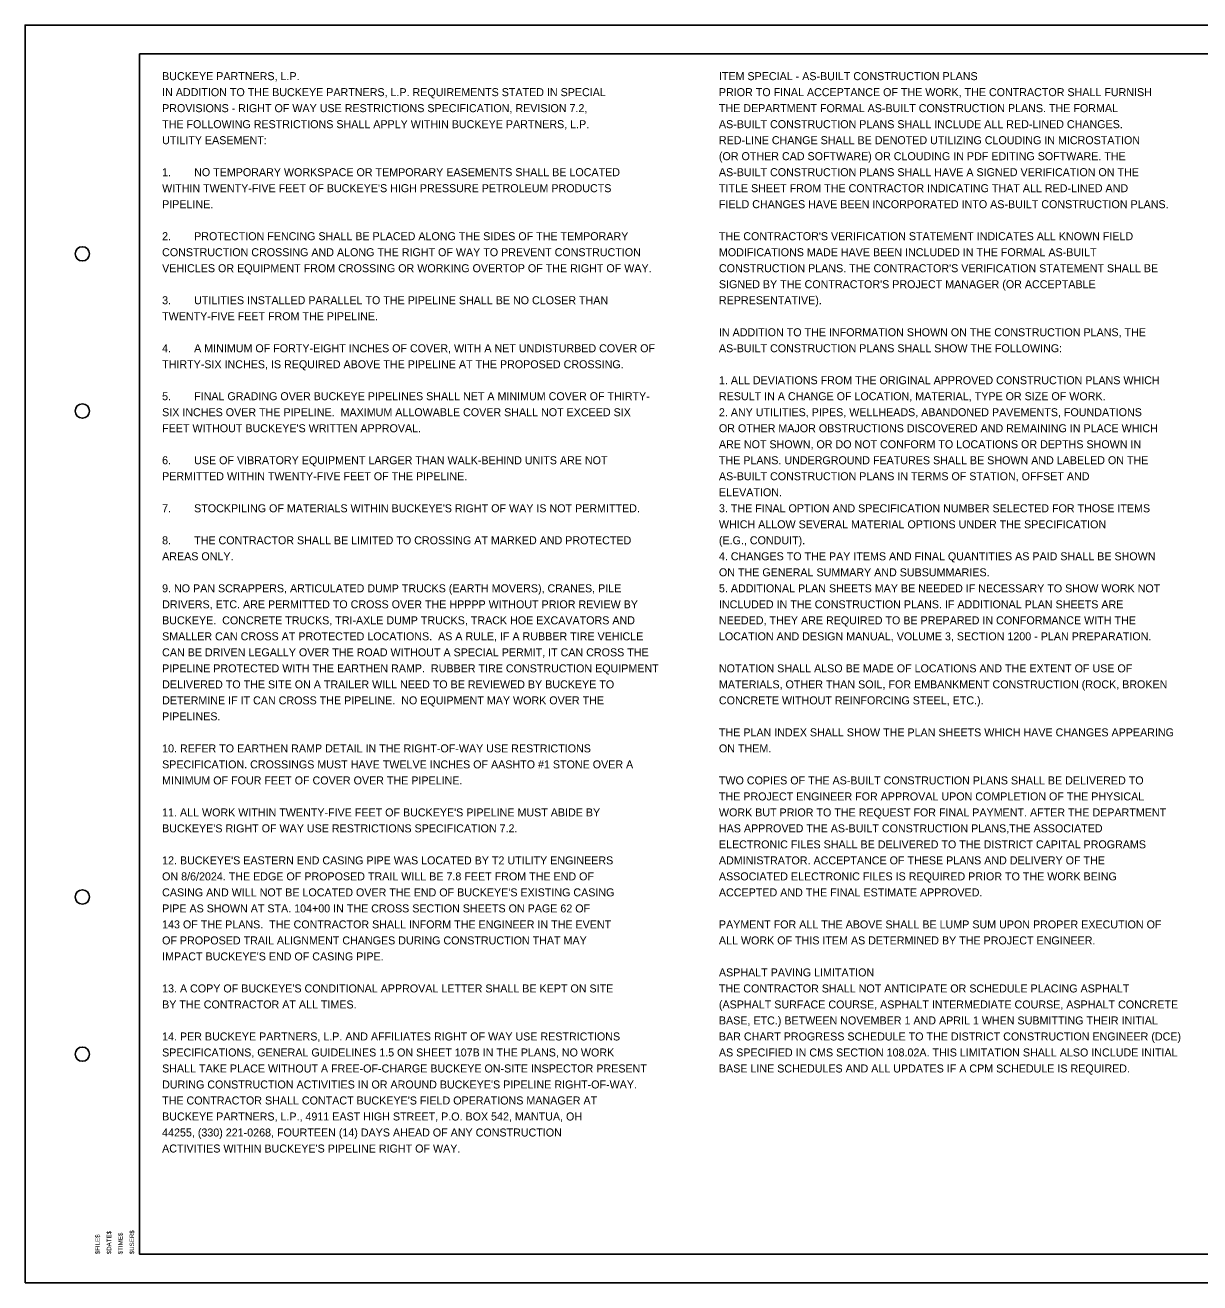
# Model space of a CAD drawing. Extents: x -16 to 195, y -13 to 9.
# Drawn here: x 160.56 to 181.1, y -12.91 to 9.09 of the extents above; entities that cross this region are included whole.
import ezdxf

# ---------------------------------------------------------------- set-up
doc = ezdxf.new("R2010")
doc.units = 0
for name, color, linetype in [('SH_Border', 7, 'Continuous'), ('SH_Cut_Line', 7, 'Continuous'), ('TX_P_1', 7, 'Continuous'), ('TX_P_Misc', 7, 'Continuous')]:
    doc.layers.add(name, color=color, linetype=linetype)

msp = doc.modelspace()

# ---------------------------------------------------------------- linework, layer by layer
at = {"layer": 'SH_Border'}
msp.add_lwpolyline([(162.559, 8.593), (194.059, 8.593), (194.059, -12.407), (162.559, -12.407)], close=True, dxfattribs=at)
for centre in [(161.559, 5.093), (161.559, 2.343), (161.559, -6.157), (161.559, -8.907)]:
    msp.add_circle(centre, 0.125, dxfattribs=at)
at = {"layer": 'SH_Cut_Line'}
msp.add_lwpolyline([(160.559, -12.907), (194.559, -12.907), (194.559, 9.093), (160.559, 9.093)], close=True, dxfattribs=at)

# ---------------------------------------------------------------- texts
at = {"layer": 'TX_P_1'}
for s, p in [('BUCKEYE PARTNERS, L.P.', (162.954, 8.131)), ('ITEM SPECIAL - AS-BUILT CONSTRUCTION PLANS', (172.692, 8.131)), ('IN ADDITION TO THE BUCKEYE PARTNERS, L.P. REQUIREMENTS STATED IN SPECIAL', (162.954, 7.851)), ('PRIOR TO FINAL ACCEPTANCE OF THE WORK, THE CONTRACTOR SHALL FURNISH', (172.692, 7.851)), ('PROVISIONS - RIGHT OF WAY USE RESTRICTIONS SPECIFICATION, REVISION 7.2,', (162.954, 7.571)), ('THE DEPARTMENT FORMAL AS-BUILT CONSTRUCTION PLANS. THE FORMAL', (172.692, 7.571)), ('THE FOLLOWING RESTRICTIONS SHALL APPLY WITHIN BUCKEYE PARTNERS, L.P.', (162.954, 7.291)), ('AS-BUILT CONSTRUCTION PLANS SHALL INCLUDE ALL RED-LINED CHANGES.', (172.692, 7.291)), ('UTILITY EASEMENT:', (162.954, 7.011)), ('RED-LINE CHANGE SHALL BE DENOTED UTILIZING CLOUDING IN MICROSTATION', (172.692, 7.011)), ('(OR OTHER CAD SOFTWARE) OR CLOUDING IN PDF EDITING SOFTWARE. THE', (172.692, 6.731)), ('1.', (162.954, 6.451)), ('NO TEMPORARY WORKSPACE OR TEMPORARY EASEMENTS SHALL BE LOCATED', (163.514, 6.451)), ('AS-BUILT CONSTRUCTION PLANS SHALL HAVE A SIGNED VERIFICATION ON THE', (172.692, 6.451)), ("WITHIN TWENTY-FIVE FEET OF BUCKEYE'S HIGH PRESSURE PETROLEUM PRODUCTS", (162.954, 6.171)), ('TITLE SHEET FROM THE CONTRACTOR INDICATING THAT ALL RED-LINED AND', (172.692, 6.171)), ('PIPELINE.', (162.954, 5.891)), ('FIELD CHANGES HAVE BEEN INCORPORATED INTO AS-BUILT CONSTRUCTION PLANS.', (172.692, 5.891)), ('2.', (162.954, 5.331)), ('PROTECTION FENCING SHALL BE PLACED ALONG THE SIDES OF THE TEMPORARY', (163.514, 5.331)), ("THE CONTRACTOR'S VERIFICATION STATEMENT INDICATES ALL KNOWN FIELD", (172.692, 5.331)), ('CONSTRUCTION CROSSING AND ALONG THE RIGHT OF WAY TO PREVENT CONSTRUCTION', (162.954, 5.051)), ('MODIFICATIONS MADE HAVE BEEN INCLUDED IN THE FORMAL AS-BUILT', (172.692, 5.051)), ('VEHICLES OR EQUIPMENT FROM CROSSING OR WORKING OVERTOP OF THE RIGHT OF WAY.', (162.954, 4.771)), ("CONSTRUCTION PLANS. THE CONTRACTOR'S VERIFICATION STATEMENT SHALL BE", (172.692, 4.771)), ("SIGNED BY THE CONTRACTOR'S PROJECT MANAGER (OR ACCEPTABLE", (172.692, 4.491)), ('3.', (162.954, 4.211)), ('UTILITIES INSTALLED PARALLEL TO THE PIPELINE SHALL BE NO CLOSER THAN', (163.514, 4.211)), ('REPRESENTATIVE).', (172.692, 4.211)), ('TWENTY-FIVE FEET FROM THE PIPELINE.', (162.954, 3.931)), ('IN ADDITION TO THE INFORMATION SHOWN ON THE CONSTRUCTION PLANS, THE', (172.692, 3.651)), ('4.', (162.954, 3.371)), ('A MINIMUM OF FORTY-EIGHT INCHES OF COVER, WITH A NET UNDISTURBED COVER OF', (163.514, 3.371)), ('AS-BUILT CONSTRUCTION PLANS SHALL SHOW THE FOLLOWING:', (172.692, 3.371)), ('THIRTY-SIX INCHES, IS REQUIRED ABOVE THE PIPELINE AT THE PROPOSED CROSSING.', (162.954, 3.091)), ('1. ALL DEVIATIONS FROM THE ORIGINAL APPROVED CONSTRUCTION PLANS WHICH', (172.692, 2.812)), ('5.', (162.954, 2.532)), ('FINAL GRADING OVER BUCKEYE PIPELINES SHALL NET A MINIMUM COVER OF THIRTY-', (163.514, 2.532)), ('RESULT IN A CHANGE OF LOCATION, MATERIAL, TYPE OR SIZE OF WORK.', (172.692, 2.532)), ('SIX INCHES OVER THE PIPELINE.  MAXIMUM ALLOWABLE COVER SHALL NOT EXCEED SIX', (162.954, 2.252)), ('2. ANY UTILITIES, PIPES, WELLHEADS, ABANDONED PAVEMENTS, FOUNDATIONS', (172.692, 2.252)), ("FEET WITHOUT BUCKEYE'S WRITTEN APPROVAL.  ", (162.954, 1.972)), ('OR OTHER MAJOR OBSTRUCTIONS DISCOVERED AND REMAINING IN PLACE WHICH', (172.692, 1.972)), ('ARE NOT SHOWN, OR DO NOT CONFORM TO LOCATIONS OR DEPTHS SHOWN IN', (172.692, 1.692)), ('6.', (162.954, 1.412)), ('USE OF VIBRATORY EQUIPMENT LARGER THAN WALK-BEHIND UNITS ARE NOT', (163.514, 1.412)), ('THE PLANS. UNDERGROUND FEATURES SHALL BE SHOWN AND LABELED ON THE ', (172.692, 1.412)), ('PERMITTED WITHIN TWENTY-FIVE FEET OF THE PIPELINE.', (162.954, 1.132)), ('AS-BUILT CONSTRUCTION PLANS IN TERMS OF STATION, OFFSET AND', (172.692, 1.132)), ('ELEVATION.', (172.692, 0.852)), ('7.', (162.954, 0.572)), ("STOCKPILING OF MATERIALS WITHIN BUCKEYE'S RIGHT OF WAY IS NOT PERMITTED.", (163.514, 0.572)), ('3. THE FINAL OPTION AND SPECIFICATION NUMBER SELECTED FOR THOSE ITEMS', (172.692, 0.572)), ('WHICH ALLOW SEVERAL MATERIAL OPTIONS UNDER THE SPECIFICATION', (172.692, 0.292)), ('8.', (162.954, 0.012)), ('THE CONTRACTOR SHALL BE LIMITED TO CROSSING AT MARKED AND PROTECTED', (163.514, 0.012)), ('(E.G., CONDUIT).', (172.692, 0.012)), ('AREAS ONLY.', (162.954, -0.268)), ('4. CHANGES TO THE PAY ITEMS AND FINAL QUANTITIES AS PAID SHALL BE SHOWN', (172.692, -0.268)), ('ON THE GENERAL SUMMARY AND SUBSUMMARIES.', (172.692, -0.548)), ('9. NO PAN SCRAPPERS, ARTICULATED DUMP TRUCKS (EARTH MOVERS), CRANES, PILE', (162.954, -0.828)), ('5. ADDITIONAL PLAN SHEETS MAY BE NEEDED IF NECESSARY TO SHOW WORK NOT', (172.692, -0.828)), ('DRIVERS, ETC. ARE PERMITTED TO CROSS OVER THE HPPPP WITHOUT PRIOR REVIEW BY', (162.954, -1.108)), ('INCLUDED IN THE CONSTRUCTION PLANS. IF ADDITIONAL PLAN SHEETS ARE', (172.692, -1.108)), ('BUCKEYE.  CONCRETE TRUCKS, TRI-AXLE DUMP TRUCKS, TRACK HOE EXCAVATORS AND', (162.954, -1.388)), ('NEEDED, THEY ARE REQUIRED TO BE PREPARED IN CONFORMANCE WITH THE', (172.692, -1.388)), ('SMALLER CAN CROSS AT PROTECTED LOCATIONS.  AS A RULE, IF A RUBBER TIRE VEHICLE', (162.954, -1.668)), ('LOCATION AND DESIGN MANUAL, VOLUME 3, SECTION 1200 - PLAN PREPARATION.', (172.692, -1.668)), ('CAN BE DRIVEN LEGALLY OVER THE ROAD WITHOUT A SPECIAL PERMIT, IT CAN CROSS THE', (162.954, -1.948)), ('PIPELINE PROTECTED WITH THE EARTHEN RAMP.  RUBBER TIRE CONSTRUCTION EQUIPMENT ', (162.954, -2.228)), ('NOTATION SHALL ALSO BE MADE OF LOCATIONS AND THE EXTENT OF USE OF', (172.692, -2.228)), ('DELIVERED TO THE SITE ON A TRAILER WILL NEED TO BE REVIEWED BY BUCKEYE TO', (162.954, -2.508)), ('MATERIALS, OTHER THAN SOIL, FOR EMBANKMENT CONSTRUCTION (ROCK, BROKEN', (172.692, -2.508)), ('DETERMINE IF IT CAN CROSS THE PIPELINE.  NO EQUIPMENT MAY WORK OVER THE', (162.954, -2.788)), ('CONCRETE WITHOUT REINFORCING STEEL, ETC.).', (172.692, -2.788)), ('PIPELINES. ', (162.954, -3.068)), ('THE PLAN INDEX SHALL SHOW THE PLAN SHEETS WHICH HAVE CHANGES APPEARING', (172.692, -3.348)), ('10. REFER TO EARTHEN RAMP DETAIL IN THE RIGHT-OF-WAY USE RESTRICTIONS', (162.954, -3.628)), ('ON THEM.', (172.692, -3.628)), ('SPECIFICATION. CROSSINGS MUST HAVE TWELVE INCHES OF AASHTO #1 STONE OVER A', (162.954, -3.908)), ('MINIMUM OF FOUR FEET OF COVER OVER THE PIPELINE. ', (162.954, -4.188)), ('TWO COPIES OF THE AS-BUILT CONSTRUCTION PLANS SHALL BE DELIVERED TO', (172.692, -4.188)), ('THE PROJECT ENGINEER FOR APPROVAL UPON COMPLETION OF THE PHYSICAL', (172.692, -4.468)), ("11. ALL WORK WITHIN TWENTY-FIVE FEET OF BUCKEYE'S PIPELINE MUST ABIDE BY", (162.954, -4.748)), ('WORK BUT PRIOR TO THE REQUEST FOR FINAL PAYMENT. AFTER THE DEPARTMENT', (172.692, -4.748)), ("BUCKEYE'S RIGHT OF WAY USE RESTRICTIONS SPECIFICATION 7.2. ", (162.954, -5.027)), ('HAS APPROVED THE AS-BUILT CONSTRUCTION PLANS,THE ASSOCIATED', (172.692, -5.027)), ('ELECTRONIC FILES SHALL BE DELIVERED TO THE DISTRICT CAPITAL PROGRAMS', (172.692, -5.307)), ("12. BUCKEYE'S EASTERN END CASING PIPE WAS LOCATED BY T2 UTILITY ENGINEERS", (162.954, -5.587)), ('ADMINISTRATOR. ACCEPTANCE OF THESE PLANS AND DELIVERY OF THE ', (172.692, -5.587)), ('ON 8/6/2024. THE EDGE OF PROPOSED TRAIL WILL BE 7.8 FEET FROM THE END OF', (162.954, -5.867)), ('ASSOCIATED ELECTRONIC FILES IS REQUIRED PRIOR TO THE WORK BEING', (172.692, -5.867)), ("CASING AND WILL NOT BE LOCATED OVER THE END OF BUCKEYE'S EXISTING CASING", (162.954, -6.147)), ('ACCEPTED AND THE FINAL ESTIMATE APPROVED.', (172.692, -6.147)), ('PIPE AS SHOWN AT STA. 104+00 IN THE CROSS SECTION SHEETS ON PAGE 62 OF ', (162.954, -6.427)), ('143 OF THE PLANS.  THE CONTRACTOR SHALL INFORM THE ENGINEER IN THE EVENT', (162.954, -6.707)), ('PAYMENT FOR ALL THE ABOVE SHALL BE LUMP SUM UPON PROPER EXECUTION OF', (172.692, -6.707)), ('OF PROPOSED TRAIL ALIGNMENT CHANGES DURING CONSTRUCTION THAT MAY', (162.954, -6.987)), ('ALL WORK OF THIS ITEM AS DETERMINED BY THE PROJECT ENGINEER. ', (172.692, -6.987)), ("IMPACT BUCKEYE'S END OF CASING PIPE.", (162.954, -7.267)), ('ASPHALT PAVING LIMITATION', (172.692, -7.547)), ("13. A COPY OF BUCKEYE'S CONDITIONAL APPROVAL LETTER SHALL BE KEPT ON SITE", (162.954, -7.827)), ('THE CONTRACTOR SHALL NOT ANTICIPATE OR SCHEDULE PLACING ASPHALT', (172.692, -7.827)), ('BY THE CONTRACTOR AT ALL TIMES.', (162.954, -8.107)), ('(ASPHALT SURFACE COURSE, ASPHALT INTERMEDIATE COURSE, ASPHALT CONCRETE', (172.692, -8.107)), ('BASE, ETC.) BETWEEN NOVEMBER 1 AND APRIL 1 WHEN SUBMITTING THEIR INITIAL', (172.692, -8.387)), ('14. PER BUCKEYE PARTNERS, L.P. AND AFFILIATES RIGHT OF WAY USE RESTRICTIONS', (162.954, -8.667)), ('BAR CHART PROGRESS SCHEDULE TO THE DISTRICT CONSTRUCTION ENGINEER (DCE)', (172.692, -8.667)), ('SPECIFICATIONS, GENERAL GUIDELINES 1.5 ON SHEET 107B IN THE PLANS, NO WORK', (162.954, -8.947)), ('AS SPECIFIED IN CMS SECTION 108.02A. THIS LIMITATION SHALL ALSO INCLUDE INITIAL', (172.692, -8.947)), ('SHALL TAKE PLACE WITHOUT A FREE-OF-CHARGE BUCKEYE ON-SITE INSPECTOR PRESENT', (162.954, -9.227)), ('BASE LINE SCHEDULES AND ALL UPDATES IF A CPM SCHEDULE IS REQUIRED.', (172.692, -9.227)), ("DURING CONSTRUCTION ACTIVITIES IN OR AROUND BUCKEYE'S PIPELINE RIGHT-OF-WAY.", (162.954, -9.507)), ("THE CONTRACTOR SHALL CONTACT BUCKEYE'S FIELD OPERATIONS MANAGER AT", (162.954, -9.787)), ('BUCKEYE PARTNERS, L.P., 4911 EAST HIGH STREET, P.O. BOX 542, MANTUA, OH', (162.954, -10.067)), ('44255, (330) 221-0268, FOURTEEN (14) DAYS AHEAD OF ANY CONSTRUCTION', (162.954, -10.347)), ("ACTIVITIES WITHIN BUCKEYE'S PIPELINE RIGHT OF WAY. ", (162.954, -10.627))]:
    msp.add_text(s, height=0.14, dxfattribs=at).set_placement(p)
at = {"layer": 'TX_P_Misc'}
for s, p in [('$FILE$', (161.864, -12.407)), ('$DATE$', (162.064, -12.407)), ('$TIME$', (162.264, -12.407)), ('$USER$', (162.464, -12.407))]:
    msp.add_text(s, height=0.078, rotation=90, dxfattribs=at).set_placement(p)

doc.saveas('drawing.dxf')
